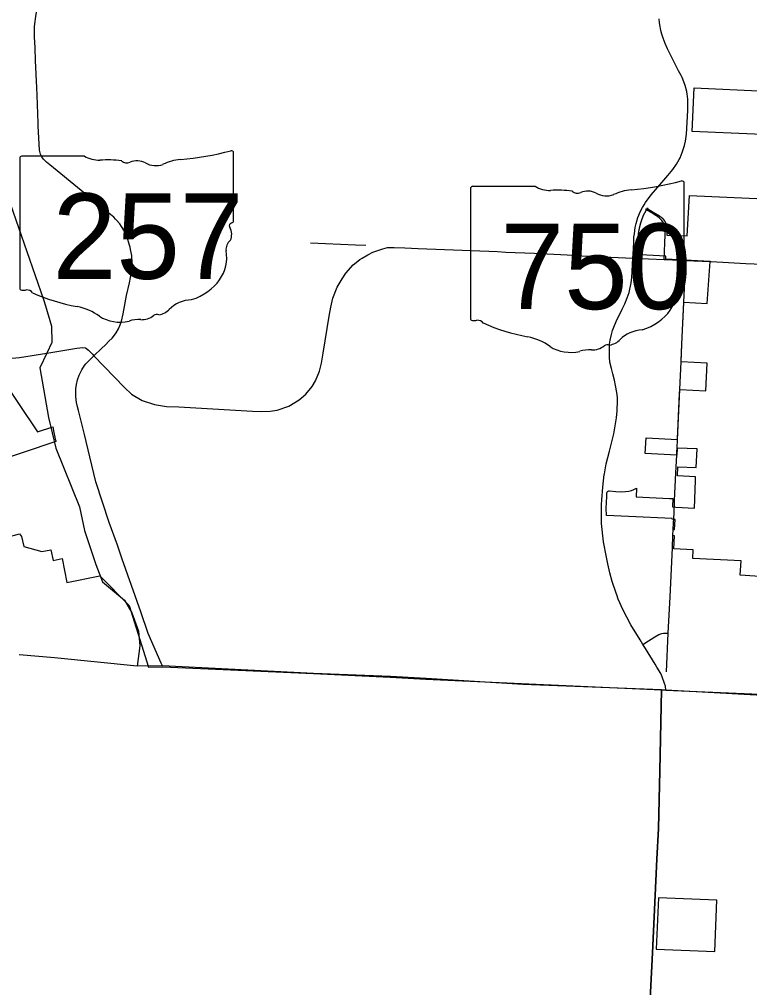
# Model space of a CAD drawing. Extents: x 1729596 to 1925846, y 659247 to 911751.
# Drawn here: x 1793175 to 1805067, y 774852 to 790627 of the extents above; entities that cross this region are included whole.
import ezdxf

# ---------------------------------------------------------------- set-up
doc = ezdxf.new("R2010")
doc.units = 0
for name, color, linetype in [('GM_X_City_Street', 7, 'Continuous'), ('GM_X_Corporation', 7, 'Continuous'), ('GM_X_County', 7, 'Continuous'), ('GM_X_County_Road', 7, 'Continuous'), ('GM_X_State_Route', 7, 'Continuous'), ('GM_X_State_Shield', 7, 'Continuous'), ('GM_X_Township', 7, 'Continuous'), ('GM_X_Township_Road', 7, 'Continuous')]:
    doc.layers.add(name, color=color, linetype=linetype)

msp = doc.modelspace()

# ---------------------------------------------------------------- linework, layer by layer
at = {"layer": 'GM_X_City_Street'}
for points in [[(1803190, 787135), (1803203, 787235), (1803218, 787303), (1803247, 787402), (1803291, 787501), (1803324, 787565), (1803349, 787606)], [(1803597, 787389), (1803567, 787415), (1803514, 787449), (1803463, 787479), (1803406, 787516), (1803371, 787537)], [(1803673, 786714), (1803691, 787115), (1803695, 787204), (1803684, 787267), (1803666, 787311), (1803637, 787353), (1803597, 787389)], [(1803183, 787078), (1803190, 787135)], [(1791652, 785213), (1791652, 785213), (1791846, 785247), (1791913, 785248), (1791970, 785240), (1792027, 785225), (1792434, 785091), (1792578, 785072), (1792635, 785066), (1792746, 785069), (1792797, 785075), (1792995, 785101), (1793175, 785121), (1793623, 785191), (1794112, 785269), (1794207, 785281), (1794252, 785276), (1794299, 785239), (1794364, 785172), (1794389, 785145)], [(1803883, 783584), (1803886, 783643), (1803892, 783784), (1803893, 783795)], [(1803836, 782580), (1803846, 782791)]]:
    msp.add_lwpolyline(points, dxfattribs=at)
at = {"layer": 'GM_X_Corporation'}
for points in [[(1806164, 788712), (1804132, 788800), (1804164, 789513), (1805912, 789433)], [(1807613, 781390), (1804914, 781573), (1804929, 781808), (1804142, 781846), (1804149, 781985), (1803831, 782002), (1803841, 782215), (1803818, 782216), (1803823, 782315), (1803845, 782314), (1803853, 782481), (1803803, 782484), (1803804, 782493), (1803097, 782529), (1802735, 782547), (1802733, 782666), (1802734, 782749), (1802739, 782860), (1802742, 782909), (1802746, 782924), (1802755, 782935), (1802764, 782942), (1802772, 782945), (1802785, 782946), (1802889, 782936), (1802976, 782930), (1803047, 782933), (1803102, 782943), (1803143, 782954), (1803183, 782967), (1803226, 782987), (1803226, 782982), (1803220, 782847), (1803760, 782822), (1803819, 782819), (1803813, 782683), (1803866, 782680), (1804171, 782665), (1804185, 783116), (1804186, 783177), (1803891, 783193), (1803898, 783339), (1804196, 783325), (1804210, 783628), (1803886, 783643), (1803881, 783530), (1803368, 783557), (1803383, 783811), (1803892, 783784), (1803931, 784596), (1804355, 784575), (1804374, 785026), (1803951, 785049), (1803964, 785338), (1803997, 786018), (1804377, 786000), (1804427, 786684), (1803703, 786721), (1803705, 786771), (1803290, 786791), (1803273, 786793), (1803254, 786804), (1803243, 786825), (1803257, 787121), (1803257, 787122), (1803257, 787124), (1803258, 787127), (1803258, 787129), (1803258, 787132), (1803259, 787134), (1803259, 787136), (1803259, 787139), (1803259, 787141), (1803260, 787144), (1803260, 787146), (1803260, 787148), (1803261, 787151), (1803261, 787152), (1803261, 787154), (1803262, 787156), (1803262, 787159), (1803262, 787161), (1803263, 787163), (1803263, 787165), (1803263, 787167), (1803264, 787170), (1803264, 787172), (1803264, 787174), (1803265, 787177), (1803265, 787178), (1803265, 787179), (1803265, 787181), (1803266, 787183), (1803266, 787184), (1803266, 787187), (1803267, 787189), (1803267, 787191), (1803268, 787194), (1803268, 787196), (1803269, 787198), (1803269, 787201), (1803269, 787203), (1803270, 787205), (1803270, 787208), (1803271, 787210), (1803271, 787212), (1803272, 787214), (1803272, 787217), (1803273, 787219), (1803273, 787221), (1803274, 787223), (1803274, 787226), (1803275, 787228), (1803275, 787231), (1803276, 787233), (1803276, 787235), (1803277, 787238), (1803277, 787240), (1803278, 787242), (1803278, 787244), (1803279, 787247), (1803279, 787249), (1803280, 787251), (1803280, 787254), (1803281, 787255), (1803281, 787256), (1803281, 787258), (1803282, 787260), (1803283, 787263), (1803283, 787265), (1803284, 787267), (1803284, 787269), (1803285, 787272), (1803285, 787274), (1803286, 787276), (1803287, 787278), (1803287, 787281), (1803288, 787283), (1803288, 787285), (1803289, 787287), (1803290, 787290), (1803290, 787292), (1803291, 787294), (1803292, 787296), (1803292, 787299), (1803293, 787301), (1803293, 787303), (1803294, 787305), (1803295, 787308), (1803296, 787310), (1803296, 787313), (1803297, 787315), (1803298, 787317), (1803298, 787320), (1803299, 787322), (1803300, 787324), (1803300, 787326), (1803301, 787328), (1803302, 787330), (1803302, 787333), (1803303, 787335), (1803304, 787337), (1803305, 787339), (1803305, 787342), (1803306, 787344), (1803307, 787346), (1803308, 787348), (1803308, 787351), (1803309, 787353), (1803310, 787355), (1803311, 787357), (1803311, 787359), (1803312, 787361), (1803313, 787363), (1803314, 787366), (1803314, 787368), (1803315, 787370), (1803316, 787372), (1803317, 787374), (1803318, 787376), (1803318, 787379), (1803319, 787381), (1803320, 787383), (1803321, 787385), (1803322, 787387), (1803322, 787390), (1803323, 787392), (1803324, 787394), (1803325, 787396), (1803326, 787398), (1803327, 787400), (1803327, 787403), (1803328, 787405), (1803329, 787407), (1803330, 787409), (1803331, 787410), (1803331, 787411), (1803332, 787413), (1803333, 787415), (1803334, 787418), (1803334, 787420), (1803335, 787422), (1803336, 787424), (1803337, 787425), (1803338, 787427), (1803338, 787429), (1803339, 787431), (1803340, 787433), (1803341, 787435), (1803342, 787437), (1803343, 787439), (1803344, 787441), (1803345, 787444), (1803346, 787446), (1803347, 787448), (1803348, 787450), (1803349, 787452), (1803350, 787454), (1803351, 787457), (1803352, 787459), (1803353, 787461), (1803353, 787463), (1803354, 787465), (1803355, 787467), (1803356, 787469), (1803357, 787471), (1803358, 787473), (1803359, 787474), (1803388, 787526), (1803405, 787557), (1803405, 787552), (1803406, 787545), (1803411, 787539), (1803495, 787487), (1803598, 787425), (1803600, 787424), (1803602, 787423), (1803604, 787422), (1803605, 787421), (1803607, 787420), (1803609, 787418), (1803610, 787417), (1803612, 787416), (1803614, 787415), (1803616, 787413), (1803617, 787412), (1803619, 787411), (1803621, 787409), (1803622, 787408), (1803624, 787407), (1803626, 787405), (1803627, 787404), (1803629, 787402), (1803631, 787401), (1803632, 787400), (1803634, 787398), (1803635, 787397), (1803637, 787396), (1803638, 787394), (1803639, 787393), (1803640, 787392), (1803641, 787393), (1803643, 787391), (1803645, 787389), (1803646, 787388), (1803648, 787386), (1803649, 787385), (1803651, 787383), (1803652, 787382), (1803653, 787380), (1803655, 787378), (1803656, 787377), (1803658, 787375), (1803659, 787373), (1803661, 787372), (1803662, 787370), (1803663, 787368), (1803665, 787367), (1803666, 787365), (1803667, 787363), (1803669, 787362), (1803670, 787360), (1803671, 787358), (1803672, 787357), (1803673, 787355), (1803674, 787353), (1803676, 787351), (1803677, 787349), (1803679, 787347), (1803680, 787345), (1803681, 787343), (1803682, 787341), (1803684, 787340), (1803685, 787338), (1803686, 787336), (1803687, 787334), (1803688, 787332), (1803689, 787330), (1803691, 787328), (1803692, 787325), (1803693, 787323), (1803694, 787321), (1803694, 787320), (1803695, 787319), (1803696, 787317), (1803697, 787315), (1803698, 787313), (1803699, 787311), (1803700, 787308), (1803701, 787306), (1803702, 787304), (1803703, 787302), (1803704, 787299), (1803705, 787297), (1803706, 787295), (1803707, 787293), (1803708, 787291), (1803708, 787289), (1803709, 787286), (1803710, 787284), (1803711, 787282), (1803711, 787280), (1803712, 787278), (1803713, 787276), (1803713, 787274), (1803714, 787272), (1803714, 787270), (1803715, 787268), (1803716, 787266), (1803716, 787263), (1803717, 787261), (1803717, 787259), (1803718, 787256), (1803719, 787254), (1803719, 787251), (1803720, 787249), (1803720, 787247), (1803721, 787244), (1803721, 787242), (1803721, 787240), (1803722, 787237), (1803725, 787211), (1803725, 787183), (1803721, 787113), (1804051, 787098), (1804086, 787756), (1805912, 787678)], [(1792848, 784829), (1793468, 783905), (1793718, 783987), (1793735, 783894), (1793754, 783819), (1793758, 783789), (1793768, 783761), (1793769, 783748), (1792200, 783224)], [(1792976, 782192), (1793178, 782246), (1793210, 782204), (1793248, 782040), (1793540, 781957), (1793687, 781987), (1793723, 781813), (1793870, 781843), (1793949, 781451), (1794488, 781561), (1794963, 781078), (1795276, 780074), (1795510, 780081), (1797967, 779971), (1799216, 779912), (1799794, 779878), (1803634, 779704), (1803603, 778383), (1803585, 777445), (1803558, 776945), (1803483, 775420), (1803430, 774349)], [(1803430, 774349), (1803483, 775420), (1803558, 776945), (1803585, 777445), (1803603, 778383), (1803634, 779704), (1803704, 779701), (1805102, 779639), (1807438, 779491), (1807843, 779471), (1807831, 779242), (1808605, 779201), (1808568, 779436), (1809792, 779366), (1810377, 779331), (1810804, 779309), (1811005, 779073), (1811178, 778662), (1811316, 777964), (1811480, 777017), (1811604, 776133), (1811724, 775429), (1811904, 774466)]]:
    msp.add_lwpolyline(points, dxfattribs=at)
msp.add_lwpolyline([(1803545, 775480), (1804498, 775441), (1804533, 776279), (1803582, 776318)], close=True, dxfattribs=at)
at = {"layer": 'GM_X_County'}
msp.add_lwpolyline([(1823936, 778682), (1818187, 778957), (1818151, 778958), (1817250, 778977), (1817214, 778979), (1811853, 779256), (1810377, 779331), (1809792, 779366), (1808550, 779443), (1807438, 779491), (1803704, 779701), (1803634, 779704), (1801375, 779790), (1799802, 779890), (1799218, 779920), (1797967, 779971), (1795507, 780094), (1795095, 780091), (1793746, 780223), (1793171, 780273)], dxfattribs=at)
at = {"layer": 'GM_X_County_Road'}
for points in [[(1803935, 788371), (1803971, 788460), (1804007, 788570), (1804024, 788645), (1804036, 788720), (1804040, 788759), (1804059, 789140), (1804062, 789184), (1804063, 789228), (1804063, 789272), (1804061, 789294), (1804060, 789315), (1804054, 789381), (1804052, 789403), (1804044, 789451), (1804017, 789548), (1803996, 789607), (1803966, 789681), (1803950, 789715), (1803911, 789790), (1803728, 790148), (1803692, 790235), (1803658, 790323), (1803639, 790384), (1803623, 790446), (1803611, 790509), (1803602, 790572), (1803596, 790635)], [(1803349, 787606), (1803369, 787642), (1803462, 787770), (1803606, 787932), (1803737, 788085), (1803814, 788179), (1803875, 788266), (1803920, 788346), (1803935, 788371)], [(1803165, 786738), (1803171, 786799), (1803181, 786998), (1803182, 787071), (1803183, 787078)], [(1802786, 785124), (1802786, 785125), (1802783, 785193), (1802783, 785284), (1802787, 785335), (1802796, 785401), (1802816, 785491), (1802835, 785557), (1802856, 785615), (1802894, 785703), (1802993, 785905), (1803037, 785995), (1803075, 786091), (1803104, 786178), (1803138, 786336), (1803147, 786415), (1803165, 786738)], [(1802912, 784293), (1802915, 784375), (1802914, 784467), (1802902, 784549), (1802883, 784663), (1802866, 784748), (1802840, 784852), (1802817, 784942), (1802792, 785045), (1802786, 785124)], [(1802853, 783877), (1802869, 783941), (1802898, 784135), (1802910, 784252), (1802912, 784293)], [(1802699, 783213), (1802701, 783225), (1802731, 783384), (1802783, 783593), (1802853, 783877)], [(1802662, 782797), (1802678, 783004), (1802699, 783213)], [(1802735, 781867), (1802687, 782113), (1802657, 782414), (1802653, 782637), (1802657, 782725), (1802662, 782797)], [(1802790, 781613), (1802757, 781756), (1802735, 781867)], [(1802902, 781253), (1802892, 781280), (1802831, 781471), (1802790, 781613)], [(1803329, 780445), (1803283, 780520), (1803135, 780763), (1803003, 781015), (1802927, 781182), (1802902, 781253)], [(1803704, 779701), (1803695, 779763), (1803683, 779808), (1803641, 779918), (1803619, 779970), (1803558, 780076), (1803531, 780123), (1803374, 780377), (1803329, 780445)]]:
    msp.add_lwpolyline(points, dxfattribs=at)
at = {"layer": 'GM_X_State_Route'}
for points in [[(1793482, 788892), (1793480, 788936), (1793465, 789394), (1793462, 789511), (1793439, 789955), (1793430, 790164), (1793422, 790343), (1793421, 790408), (1793422, 790509), (1793431, 790592), (1793438, 790637), (1793462, 790782), (1793496, 790992), (1793514, 791113), (1793528, 791294), (1793538, 791541), (1793538, 791555), (1793540, 791608)], [(1794742, 787374), (1794713, 787404), (1794657, 787446), (1794560, 787525), (1794180, 787838), (1793670, 788258), (1793616, 788302), (1793599, 788317), (1793583, 788334), (1793568, 788352), (1793542, 788390), (1793521, 788431), (1793513, 788453), (1793507, 788475), (1793501, 788498), (1793482, 788892)], [(1794118, 784339), (1794108, 784387), (1794096, 784481), (1794092, 784545), (1794094, 784609), (1794105, 784679), (1794124, 784754), (1794151, 784831), (1794194, 784920), (1794238, 784987), (1794258, 785013), (1794315, 785075), (1794389, 785145), (1794514, 785266), (1794577, 785327), (1794632, 785382), (1794684, 785436), (1794724, 785485), (1794751, 785519), (1794792, 785587), (1794817, 785650), (1794836, 785711), (1794863, 785829), (1794920, 786128), (1794966, 786337), (1795000, 786509), (1795009, 786575), (1795013, 786656), (1795006, 786778), (1794987, 786877), (1794979, 786918), (1794965, 786964), (1794939, 787040), (1794910, 787120), (1794876, 787194), (1794841, 787254), (1794811, 787296), (1794758, 787358), (1794742, 787374)], [(1794389, 785145), (1794886, 784632), (1795001, 784522), (1795176, 784416), (1795374, 784351), (1795569, 784322), (1795771, 784315), (1796971, 784245), (1797112, 784239), (1797258, 784243), (1797375, 784261), (1797561, 784324), (1797734, 784427), (1797838, 784522), (1797943, 784647), (1797995, 784740), (1798062, 784897), (1798096, 785025), (1798125, 785191), (1798222, 785793), (1798249, 785937), (1798282, 786087), (1798350, 786265), (1798431, 786402), (1798491, 786492), (1798613, 786628), (1798659, 786667), (1798722, 786715), (1798759, 786739), (1798849, 786793), (1798930, 786835), (1799046, 786874), (1799093, 786887)], [(1799093, 786887), (1799169, 786908), (1799276, 786913), (1799453, 786905), (1799667, 786894)], [(1799667, 786894), (1800960, 786843), (1801095, 786835), (1801559, 786816), (1802308, 786779), (1802336, 786777)], [(1802336, 786777), (1803165, 786738), (1803673, 786714)], [(1803673, 786714), (1803702, 786714), (1804026, 786700), (1804427, 786684), (1804441, 786683)], [(1804441, 786683), (1805006, 786649), (1806106, 786604), (1806408, 786590), (1806429, 786589), (1806951, 786560), (1807360, 786549), (1807446, 786547), (1807709, 786531), (1808840, 786478), (1810274, 786407), (1811167, 786357), (1811832, 786309), (1812210, 786294), (1812953, 786246)], [(1795507, 780094), (1795485, 780137), (1795271, 780621), (1795152, 780977), (1794999, 781404), (1794849, 781834), (1794774, 782063), (1794638, 782430), (1794422, 783094), (1794321, 783501), (1794234, 783865), (1794136, 784253), (1794118, 784339)]]:
    msp.add_lwpolyline(points, dxfattribs=at)
at = {"layer": 'GM_X_State_Shield'}
for p, q in [((1796663, 787347), (1796663, 788453)), ((1796663, 787347), (1796663, 788453)), ((1793183, 788364), (1793183, 786251)), ((1793183, 788364), (1793183, 786251)), ((1794236, 788400), (1793217, 788400)), ((1794236, 788400), (1793217, 788400)), ((1800522, 787871), (1800522, 785758)), ((1800522, 787871), (1800522, 785758)), ((1801575, 787907), (1800556, 787907)), ((1801575, 787907), (1800556, 787907)), ((1804002, 786854), (1804002, 787960)), ((1804002, 786854), (1804002, 787960)), ((1796663, 787347), (1796663, 787347)), ((1796663, 787347), (1796663, 787347)), ((1804002, 786855), (1804002, 786854)), ((1804002, 786855), (1804002, 786854))]:
    msp.add_line(p, q, dxfattribs=at)
for centre, major_axis, start_param, end_param in [((1795423, 791281), (3691, 0), 4.814394, 5.042369), ((1795423, 791281), (3691, 0), 4.814394, 5.042369), ((1796624, 788457), (38.7, 0), 6.141152, 7.989035), ((1796624, 788457), (38.7, 0), 6.141152, 7.989035), ((1793222, 788368), (40.3, 0), 1.712693, 3.28349), ((1793222, 788368), (40.3, 0), 1.712693, 3.28349), ((1794479, 788646), (391, 0), 4.042523, 4.731795), ((1794479, 788646), (391, 0), 4.042523, 4.731795), ((1794609, 787214), (1404, 0), 1.404758, 1.657858), ((1794609, 787214), (1404, 0), 1.404758, 1.657858), ((1794927, 788379), (113, 0), 3.836095, 5.185415), ((1794927, 788379), (113, 0), 3.836095, 5.185415), ((1795093, 788135), (235, 0), 0.950623, 2.079405), ((1795093, 788135), (235, 0), 0.950623, 2.079405), ((1795396, 788470), (282, 0), 4.081561, 5.145723), ((1795396, 788470), (282, 0), 4.081561, 5.145723), ((1795894, 787755), (743, 0), 1.699011, 2.107814), ((1795894, 787755), (743, 0), 1.699011, 2.107814), ((1802762, 790789), (3691, 0), 4.814394, 5.042369), ((1802762, 790789), (3691, 0), 4.814394, 5.042369), ((1803964, 787964), (38.7, 0), 6.141152, 7.989035), ((1803964, 787964), (38.7, 0), 6.141152, 7.989035), ((1800562, 787876), (40.3, 0), 1.712693, 3.28349), ((1800562, 787876), (40.3, 0), 1.712693, 3.28349), ((1801818, 788153), (391, 0), 4.042523, 4.731795), ((1801818, 788153), (391, 0), 4.042523, 4.731795), ((1801948, 786721), (1404, 0), 1.404758, 1.657858), ((1801948, 786721), (1404, 0), 1.404758, 1.657858), ((1802266, 787887), (113, 0), 3.836095, 5.185415), ((1802266, 787887), (113, 0), 3.836095, 5.185415), ((1802432, 787642), (235, 0), 0.950623, 2.079405), ((1802432, 787642), (235, 0), 0.950623, 2.079405), ((1803233, 787262), (743, 0), 1.699011, 2.107814), ((1803233, 787262), (743, 0), 1.699011, 2.107814), ((1802735, 787977), (282, 0), 4.081561, 5.145723), ((1802735, 787977), (282, 0), 4.081561, 5.145723), ((1796622, 787343), (41.5, 0), 5.05454, 6.418171), ((1796622, 787343), (41.5, 0), 5.05454, 6.418171), ((1796654, 787266), (60, 0), 1.883978, 3.671073), ((1796654, 787266), (60, 0), 1.883978, 3.671073), ((1796273, 787126), (360, 0), 5.934695, 6.695948), ((1796273, 787126), (360, 0), 5.934695, 6.695948), ((1796802, 786885), (262, 0), 2.387724, 3.262537), ((1796802, 786885), (262, 0), 2.387724, 3.262537), ((1795630, 786744), (923, 0), 5.101752, 6.440018), ((1795630, 786744), (923, 0), 5.101752, 6.440018), ((1803993, 786773), (60, 0), 1.883978, 3.671073), ((1803993, 786773), (60, 0), 1.883978, 3.671073), ((1803612, 786633), (360, 0), 5.934695, 6.695948), ((1803612, 786633), (360, 0), 5.934695, 6.695948), ((1803961, 786850), (41.5, 0), 5.05454, 6.418171), ((1803961, 786850), (41.5, 0), 5.05454, 6.418171), ((1804141, 786392), (262, 0), 2.387724, 3.262537), ((1804141, 786392), (262, 0), 2.387724, 3.262537), ((1793223, 786246), (40.7, 0), 3.00124, 4.508301), ((1793223, 786246), (40.7, 0), 3.00124, 4.508301), ((1802969, 786251), (923, 0), 5.101752, 6.440018), ((1802969, 786251), (923, 0), 5.101752, 6.440018), ((1793229, 786462), (310, 0), 4.665946, 4.897461), ((1793229, 786462), (310, 0), 4.665946, 4.897461), ((1793293, 786129), (112, 0), 0.519207, 1.627899), ((1793293, 786129), (112, 0), 0.519207, 1.627899), ((1794706, 788027), (2665, 0), 4.195997, 4.488961), ((1794706, 788027), (2665, 0), 4.195997, 4.488961), ((1793911, 785301), (834, 0), 0.823519, 1.323587), ((1793911, 785301), (834, 0), 0.823519, 1.323587), ((1796019, 785657), (506, 0), 1.647645, 2.488434), ((1796019, 785657), (506, 0), 1.647645, 2.488434), ((1794813, 786118), (529, 0), 4.026481, 4.996735), ((1794813, 786118), (529, 0), 4.026481, 4.996735), ((1795157, 785960), (282, 0), 4.691044, 5.507374), ((1795157, 785960), (282, 0), 4.691044, 5.507374), ((1795413, 785755), (79.4, 0), 1.147584, 2.315152), ((1795413, 785755), (79.4, 0), 1.147584, 2.315152), ((1795379, 786046), (298, 0), 4.937069, 5.64225), ((1795379, 786046), (298, 0), 4.937069, 5.64225), ((1800562, 785753), (40.7, 0), 3.00124, 4.508301), ((1800562, 785753), (40.7, 0), 3.00124, 4.508301), ((1795119, 785388), (435, 0), 1.495662, 1.94098), ((1795119, 785388), (435, 0), 1.495662, 1.94098), ((1800568, 785969), (310, 0), 4.665946, 4.897461), ((1800568, 785969), (310, 0), 4.665946, 4.897461), ((1800632, 785636), (112, 0), 0.519207, 1.627899), ((1800632, 785636), (112, 0), 0.519207, 1.627899), ((1802045, 787535), (2665, 0), 4.195997, 4.488961), ((1802045, 787535), (2665, 0), 4.195997, 4.488961), ((1801250, 784808), (834, 0), 0.823519, 1.323587), ((1801250, 784808), (834, 0), 0.823519, 1.323587), ((1803358, 785165), (506, 0), 1.647645, 2.488434), ((1803358, 785165), (506, 0), 1.647645, 2.488434), ((1802152, 785625), (529, 0), 4.026481, 4.996735), ((1802152, 785625), (529, 0), 4.026481, 4.996735), ((1802497, 785467), (282, 0), 4.691044, 5.507374), ((1802497, 785467), (282, 0), 4.691044, 5.507374), ((1802752, 785262), (79.4, 0), 1.147584, 2.315152), ((1802752, 785262), (79.4, 0), 1.147584, 2.315152), ((1802718, 785553), (298, 0), 4.937069, 5.64225), ((1802718, 785553), (298, 0), 4.937069, 5.64225), ((1802458, 784895), (435, 0), 1.495662, 1.94098), ((1802458, 784895), (435, 0), 1.495662, 1.94098)]:
    msp.add_ellipse(centre, major_axis=major_axis, ratio=0.8, start_param=start_param, end_param=end_param, dxfattribs=at)
at = {"layer": 'GM_X_Township'}
for points in [[(1793028, 787628), (1793570, 786064), (1793601, 785958), (1793697, 785627), (1793703, 785362), (1793623, 785191), (1793510, 784951), (1793649, 784141), (1793768, 783640), (1794157, 782687), (1794235, 782300), (1794422, 781746), (1794530, 781465), (1794889, 781166), (1795007, 780959), (1795116, 780658), (1795136, 780423), (1795095, 780091)], [(1795507, 780094), (1795095, 780091)]]:
    msp.add_lwpolyline(points, dxfattribs=at)
at = {"layer": 'GM_X_Township_Road'}
for points in [[(1797916, 786989), (1798651, 786955), (1798816, 786947)], [(1803997, 786013), (1803997, 786018), (1804026, 786700)], [(1803951, 785063), (1803964, 785338), (1803997, 786013)], [(1803927, 784534), (1803930, 784596), (1803951, 785047), (1803951, 785063)], [(1803893, 783795), (1803927, 784534)], [(1803882, 783531), (1803883, 783584)], [(1803846, 782791), (1803868, 783240), (1803881, 783530), (1803882, 783531)], [(1803828, 782422), (1803836, 782580)], [(1803741, 780626), (1803775, 781220), (1803813, 782017), (1803818, 782219), (1803823, 782315), (1803823, 782316)], [(1803823, 782316), (1803828, 782422)], [(1803329, 780445), (1803420, 780503), (1803464, 780529), (1803521, 780565), (1803588, 780605), (1803604, 780613), (1803620, 780619), (1803636, 780623), (1803662, 780626), (1803688, 780628), (1803741, 780626)], [(1803716, 779995), (1803741, 780626)]]:
    msp.add_lwpolyline(points, dxfattribs=at)

# ---------------------------------------------------------------- texts
at = {"layer": 'GM_X_State_Shield'}
for s, p in [('257', (1793718, 786400)), ('257', (1793718, 786400)), ('750', (1801011, 785907)), ('750', (1801011, 785907))]:
    msp.add_text(s, height=1392.2, dxfattribs=at).set_placement(p)

doc.saveas('drawing.dxf')
